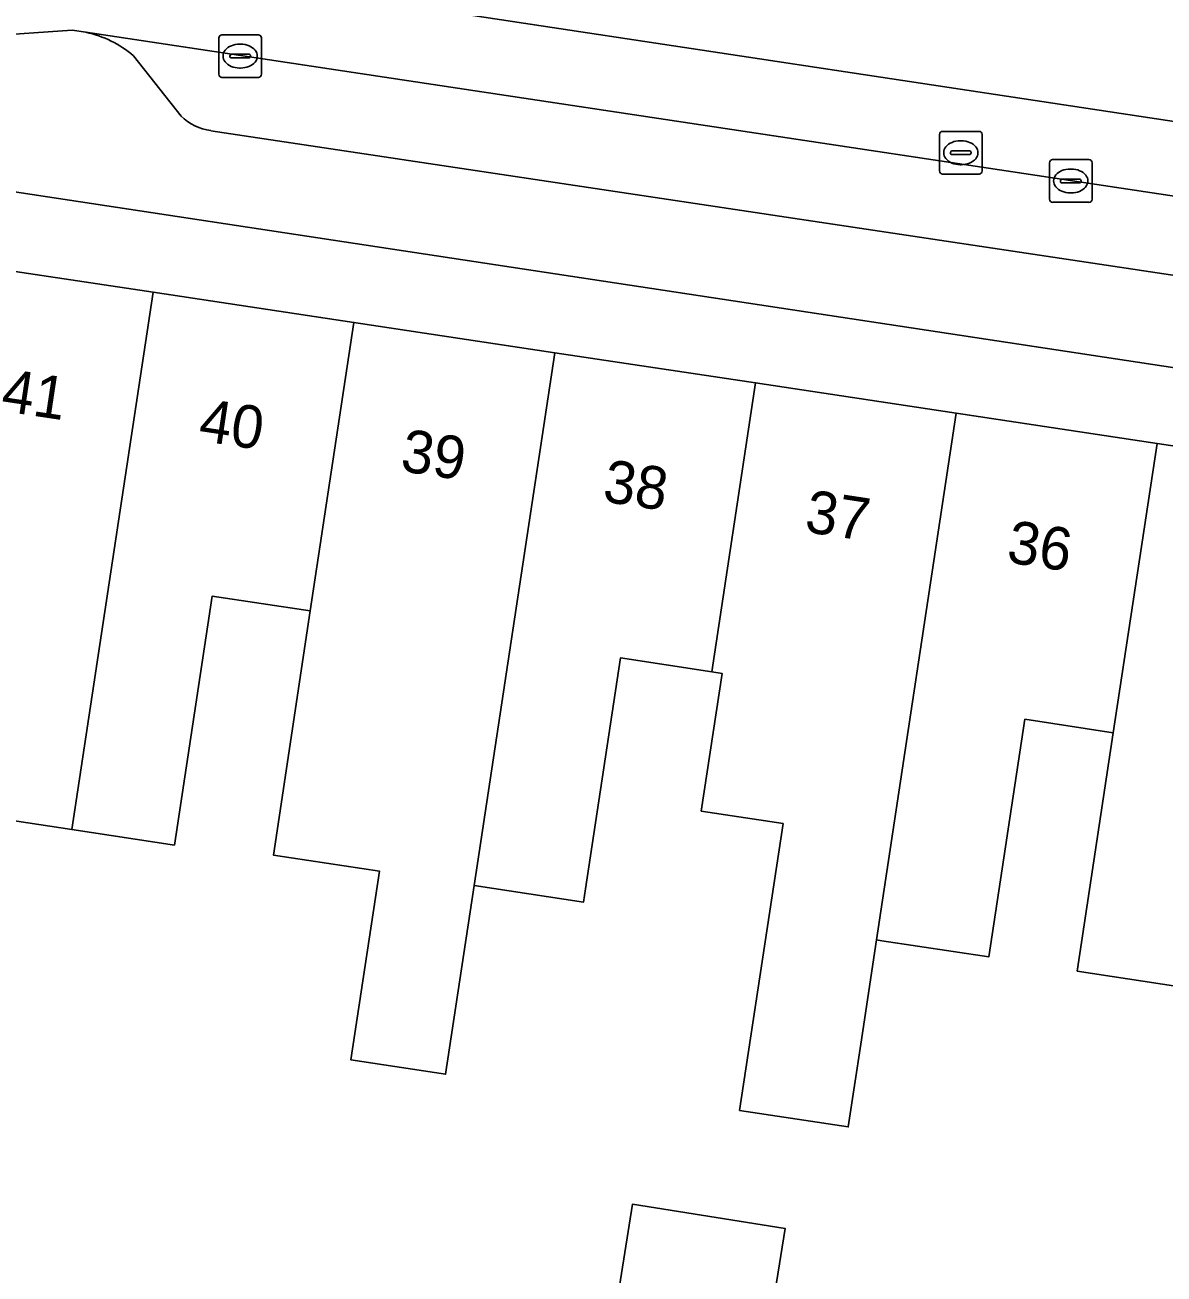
# Model space of a CAD drawing. Extents: x 162172 to 163187, y 382874 to 383685.
# Drawn here: x 162933.89 to 162960.56, y 383251.64 to 383280.9 of the extents above; entities that cross this region are included whole.
import ezdxf

# ---------------------------------------------------------------- set-up
doc = ezdxf.new("R2010")
doc.units = 0
for name, color, linetype in [('IMGEO_Erf', 7, 'Continuous'), ('IMGEO_Kolk', 7, 'Continuous'), ('IMGEO_Pand', 7, 'Continuous'), ('IMGEO_Pand_nummerreeks', 7, 'Continuous'), ('IMGEO_Parkeervlak_open', 7, 'Continuous'), ('IMGEO_Rijbaan_lokaal_gesloten', 7, 'Continuous'), ('IMGEO_Rioolput', 7, 'Continuous'), ('IMGEO_Voetpad_open', 7, 'Continuous')]:
    doc.layers.add(name, color=color, linetype=linetype)

msp = doc.modelspace()

# ---------------------------------------------------------------- linework, layer by layer
at = {"layer": 'IMGEO_Erf'}
for points in [[(162978.626, 383270.167), (162932.146, 383277.218)], [(162930.093, 383276.055), (162930.093, 383275.66), (162932.35, 383275.32), (162936.892, 383274.636), (162941.594, 383273.928), (162946.296, 383273.22), (162950.997, 383272.512), (162955.7, 383271.804), (162960.402, 383271.096), (162965.104, 383270.388), (162969.805, 383269.68), (162974.508, 383268.972), (162979.454, 383268.227), (162979.583, 383269.208)], [(162960.89, 383258.376), (162958.532, 383258.734), (162959.377, 383264.319), (162957.306, 383264.633), (162956.462, 383259.067), (162953.96, 383259.447), (162953.833, 383259.466), (162953.463, 383257.021), (162953.17, 383255.084), (162950.627, 383255.472), (162951.645, 383262.19), (162949.728, 383262.481), (162950.217, 383265.709), (162949.974, 383265.746), (162947.836, 383266.07), (162947.017, 383260.665), (162946.969, 383260.349), (162944.408, 383260.738), (162943.739, 383256.319), (162941.524, 383256.655), (162942.194, 383261.074), (162939.707, 383261.452), (162940.572, 383267.172), (162938.276, 383267.52), (162937.391, 383261.685), (162934.989, 383262.05), (162932.66, 383262.403)], [(162947.478, 383249.241), (162948.119, 383253.277), (162951.69, 383252.707), (162951.047, 383248.672)]]:
    msp.add_lwpolyline(points, dxfattribs=at)
at = {"layer": 'IMGEO_Kolk'}
for p, q in [((162938.429, 383279.741), (162938.429, 383280.593)), ((162938.504, 383280.667), (162939.356, 383280.667)), ((162939.43, 383280.593), (162939.43, 383279.741)), ((162938.917, 383280.447), (162938.942, 383280.447)), ((162938.688, 383280.161), (162938.688, 383280.173)), ((162939.126, 383280.124), (162938.728, 383280.124)), ((162938.731, 383280.21), (162939.129, 383280.21)), ((162939.172, 383280.173), (162939.172, 383280.161)), ((162938.94, 383279.887), (162938.915, 383279.887)), ((162939.356, 383279.667), (162938.504, 383279.667)), ((162957.88, 383276.816), (162957.88, 383277.668)), ((162957.955, 383277.742), (162958.807, 383277.742)), ((162958.881, 383277.668), (162958.881, 383276.816)), ((162958.368, 383277.522), (162958.393, 383277.522)), ((162958.139, 383277.236), (162958.139, 383277.248)), ((162958.577, 383277.199), (162958.179, 383277.199)), ((162958.182, 383277.285), (162958.58, 383277.285)), ((162958.623, 383277.248), (162958.623, 383277.236)), ((162958.391, 383276.962), (162958.366, 383276.962)), ((162958.807, 383276.742), (162957.955, 383276.742))]:
    msp.add_line(p, q, dxfattribs=at)
for points in [[(162938.429, 383279.741), (162938.429, 383280.593)], [(162938.504, 383280.667), (162939.356, 383280.667)], [(162939.43, 383280.593), (162939.43, 383279.741)], [(162939.356, 383279.667), (162938.504, 383279.667)], [(162957.88, 383276.816), (162957.88, 383277.668)], [(162957.955, 383277.742), (162958.807, 383277.742)], [(162958.881, 383277.668), (162958.881, 383276.816)], [(162958.807, 383276.742), (162957.955, 383276.742)]]:
    msp.add_lwpolyline(points, dxfattribs=at)
for centre, radius, start, end in [((162938.506, 383280.591), 0.0765, 91.552, 178.448), ((162938.506, 383280.591), 0.0765, 91.552, 178.448), ((162939.354, 383280.591), 0.0765, 1.552, 88.448), ((162939.354, 383280.591), 0.0765, 1.552, 88.448), ((162938.728, 383280.17), 0.0403, 85.8775, 175.7526), ((162938.725, 383280.16), 0.0366, 178.938, 274.7102), ((162939.129, 383280.167), 0.043, 264.8664, 352.4533), ((162939.133, 383280.172), 0.0386, 1.7309, 96.639), ((162938.506, 383279.743), 0.0765, 181.552, 268.448), ((162938.506, 383279.743), 0.0765, 181.552, 268.448), ((162939.354, 383279.743), 0.0765, 271.552, 358.448), ((162939.354, 383279.743), 0.0765, 271.552, 358.448), ((162957.957, 383277.666), 0.0765, 91.552, 178.448), ((162957.957, 383277.666), 0.0765, 91.552, 178.448), ((162958.805, 383277.666), 0.0765, 1.552, 88.448), ((162958.805, 383277.666), 0.0765, 1.552, 88.448), ((162958.179, 383277.245), 0.0403, 85.8775, 175.7526), ((162958.176, 383277.235), 0.0366, 178.938, 274.7102), ((162958.58, 383277.242), 0.043, 264.8664, 352.4533), ((162958.584, 383277.247), 0.0386, 1.7309, 96.639), ((162957.957, 383276.818), 0.0765, 181.552, 268.448), ((162957.957, 383276.818), 0.0765, 181.552, 268.448), ((162958.805, 383276.818), 0.0765, 271.552, 358.448), ((162958.805, 383276.818), 0.0765, 271.552, 358.448)]:
    msp.add_arc(centre, radius, start, end, dxfattribs=at)
for centre, major_axis, ratio, start_param, end_param in [((162938.916, 383280.167), (-0.387, 0.002), 0.722429, 4.712389, 7.853982), ((162938.941, 383280.167), (-0.39, 0.002), 0.717154, 1.570796, 4.712389), ((162958.367, 383277.242), (-0.387, 0.002), 0.722429, 4.712389, 7.853982), ((162958.392, 383277.242), (-0.39, 0.002), 0.717154, 1.570796, 4.712389)]:
    msp.add_ellipse(centre, major_axis=major_axis, ratio=ratio, start_param=start_param, end_param=end_param, dxfattribs=at)
at = {"layer": 'IMGEO_Pand'}
for points in [[(162936.892, 383274.636), (162932.35, 383275.32), (162931.329, 383268.574), (162931.436, 383268.558), (162933.544, 383268.238), (162932.66, 383262.403), (162934.989, 383262.05)], [(162940.572, 383267.172), (162941.594, 383273.928), (162936.892, 383274.636), (162934.989, 383262.05), (162937.391, 383261.685), (162938.276, 383267.52)], [(162946.296, 383273.22), (162941.594, 383273.928), (162940.572, 383267.172), (162939.707, 383261.452), (162942.194, 383261.074), (162941.524, 383256.655), (162943.739, 383256.319), (162944.408, 383260.738)], [(162950.997, 383272.512), (162946.296, 383273.22), (162944.408, 383260.738), (162946.969, 383260.349), (162947.017, 383260.665), (162947.836, 383266.07), (162949.974, 383265.746)], [(162955.7, 383271.804), (162950.997, 383272.512), (162949.974, 383265.746), (162950.217, 383265.709), (162949.728, 383262.481), (162951.645, 383262.19), (162950.627, 383255.472), (162953.17, 383255.084), (162953.463, 383257.021), (162953.833, 383259.466)], [(162957.306, 383264.633), (162959.377, 383264.319), (162960.402, 383271.096), (162955.7, 383271.804), (162953.833, 383259.466), (162953.96, 383259.447), (162956.462, 383259.067)], [(162965.104, 383270.388), (162960.402, 383271.096), (162959.377, 383264.319), (162958.532, 383258.734), (162960.89, 383258.376), (162963.232, 383258.02)], [(162951.595, 383248.584), (162951.047, 383248.672), (162951.69, 383252.707), (162948.119, 383253.277), (162947.478, 383249.241), (162946.982, 383245.956), (162951.072, 383245.304)]]:
    msp.add_lwpolyline(points, close=True, dxfattribs=at)
at = {"layer": 'IMGEO_Parkeervlak_open'}
for points in [[(162975.936, 383274.527), (162973.133, 383275.028), (162935.314, 383280.725)], [(162936.434, 383280.174), (162937.549, 383278.762)], [(162938.244, 383278.42), (162972.998, 383273.201)]]:
    msp.add_lwpolyline(points, dxfattribs=at)
for centre, radius, start, end in [((162934.767, 383278.199), 2.585, 49.8328, 77.7762), ((162938.413, 383279.642), 1.233, 225.4969, 262.1007)]:
    msp.add_arc(centre, radius, start, end, dxfattribs=at)
at = {"layer": 'IMGEO_Rijbaan_lokaal_gesloten'}
for points in [[(163040.344, 383282.562), (163020.844, 383276.695), (163009.736, 383273.624), (163003.62, 383272.424), (163000.382, 383272.424), (162997.504, 383272.791), (162988.869, 383274.025), (162979.785, 383275.484), (162963.075, 383278.288), (162940.869, 383281.654)], [(162940.869, 383281.654), (162963.075, 383278.288), (162979.785, 383275.484), (162988.869, 383274.025), (162997.504, 383272.791), (163000.382, 383272.424), (163003.62, 383272.424), (163009.736, 383273.624), (163020.844, 383276.695), (163040.344, 383282.562)], [(162932.962, 383280.637), (162934.995, 383280.773), (162935.314, 383280.725), (162973.133, 383275.028), (162975.936, 383274.527), (162978.681, 383274.105), (162990.964, 383272.214), (162992.596, 383271.991), (162993.768, 383271.831), (162996.284, 383271.485), (163000, 383271.063), (163000.379, 383271.02)]]:
    msp.add_lwpolyline(points, dxfattribs=at)
at = {"layer": 'IMGEO_Rioolput'}
for p, q in [((162955.305, 383277.478), (162955.305, 383278.33)), ((162955.38, 383278.404), (162956.232, 383278.404)), ((162956.306, 383278.33), (162956.306, 383277.478)), ((162955.607, 383277.947), (162956.005, 383277.947)), ((162955.793, 383278.184), (162955.818, 383278.184)), ((162955.564, 383277.898), (162955.564, 383277.91)), ((162956.002, 383277.861), (162955.604, 383277.861)), ((162956.048, 383277.91), (162956.048, 383277.898)), ((162956.232, 383277.404), (162955.38, 383277.404)), ((162955.816, 383277.624), (162955.791, 383277.624))]:
    msp.add_line(p, q, dxfattribs=at)
for points in [[(162955.305, 383277.478), (162955.305, 383278.33)], [(162955.38, 383278.404), (162956.232, 383278.404)], [(162956.306, 383278.33), (162956.306, 383277.478)], [(162956.232, 383277.404), (162955.38, 383277.404)]]:
    msp.add_lwpolyline(points, dxfattribs=at)
for centre, radius, start, end in [((162955.382, 383278.328), 0.0765, 91.552, 178.448), ((162955.382, 383278.328), 0.0765, 91.552, 178.448), ((162956.23, 383278.328), 0.0765, 1.552, 88.448), ((162956.23, 383278.328), 0.0765, 1.552, 88.448), ((162955.604, 383277.907), 0.0403, 85.8775, 175.7526), ((162956.009, 383277.909), 0.0386, 1.7309, 96.639), ((162955.601, 383277.897), 0.0366, 178.938, 274.7102), ((162956.005, 383277.904), 0.043, 264.8664, 352.4533), ((162955.382, 383277.48), 0.0765, 181.552, 268.448), ((162955.382, 383277.48), 0.0765, 181.552, 268.448), ((162956.23, 383277.48), 0.0765, 271.552, 358.448), ((162956.23, 383277.48), 0.0765, 271.552, 358.448)]:
    msp.add_arc(centre, radius, start, end, dxfattribs=at)
for centre, major_axis, ratio, start_param, end_param in [((162955.792, 383277.904), (-0.387, 0.002), 0.722429, 4.712389, 7.853982), ((162955.817, 383277.904), (-0.39, 0.002), 0.717154, 1.570796, 4.712389)]:
    msp.add_ellipse(centre, major_axis=major_axis, ratio=ratio, start_param=start_param, end_param=end_param, dxfattribs=at)
at = {"layer": 'IMGEO_Voetpad_open'}
for points in [[(162935.314, 383280.725), (162934.995, 383280.773), (162932.962, 383280.637), (162930.976, 383280.432), (162929.847, 383280.24), (162924.452, 383279.503)], [(162937.549, 383278.762), (162936.434, 383280.174)], [(162972.998, 383273.201), (162938.244, 383278.42)], [(162932.146, 383277.218), (162978.626, 383270.167)]]:
    msp.add_lwpolyline(points, dxfattribs=at)
for centre, radius, start, end in [((162934.767, 383278.199), 2.585, 49.8328, 77.7762), ((162938.413, 383279.642), 1.233, 225.4969, 262.1007)]:
    msp.add_arc(centre, radius, start, end, dxfattribs=at)

# ---------------------------------------------------------------- texts
at = {"layer": 'IMGEO_Pand_nummerreeks'}
for s, rotation, p in [('41', 351.4343, (162933.304, 383271.86)), ('40', 351.4361, (162937.927, 383271.163)), ('39', 351.4343, (162942.656, 383270.452)), ('38', 351.4343, (162947.391, 383269.738)), ('37', 351.4343, (162952.121, 383269.027)), ('36', 351.4343, (162956.853, 383268.314))]:
    msp.add_text(s, height=1, rotation=rotation, dxfattribs=at).set_placement(p)

doc.saveas('drawing.dxf')
